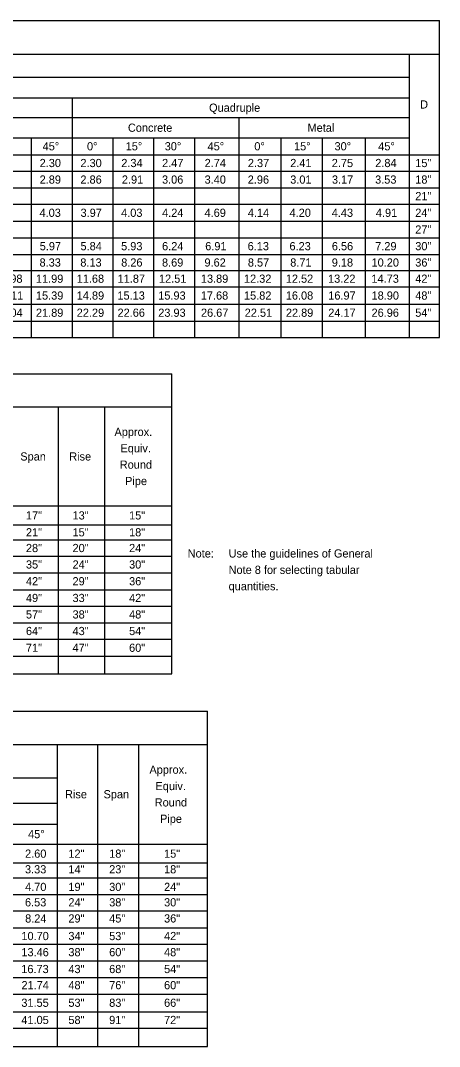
# Model space of a CAD drawing. Extents: x 10029 to 10796, y 10063 to 10519.
# Drawn here: x 10616.8 to 10795.9, y 10063.2 to 10502 of the extents above; entities that cross this region are included whole.
import ezdxf

# ---------------------------------------------------------------- set-up
doc = ezdxf.new("R2010")
doc.units = 0
doc.layers.add('Default', color=7, linetype='Continuous')
doc.layers.add('Dimension', color=7, linetype='Continuous')

msp = doc.modelspace()

# ---------------------------------------------------------------- linework, layer by layer
at = {"layer": 'Default'}
for p, q in [((10028.97, 10502.01), (10795.89, 10502.01)), ((10795.89, 10366.47), (10795.89, 10502.01)), ((10028.97, 10487.65), (10795.89, 10487.65)), ((10783.03, 10366.47), (10783.03, 10487.65)), ((10326.86, 10477.72), (10783.03, 10477.72)), ((10326.86, 10468.97), (10783.03, 10468.97)), ((10638.95, 10366.47), (10638.95, 10468.97)), ((10042.36, 10460.49), (10783.03, 10460.49)), ((10710.2, 10366.47), (10710.2, 10460.49)), ((10244.78, 10451.88), (10783.03, 10451.88)), ((10621.51, 10366.47), (10621.51, 10451.88)), ((10656.39, 10366.47), (10656.39, 10451.88)), ((10673.82, 10366.47), (10673.82, 10451.88)), ((10691.26, 10366.47), (10691.26, 10451.88)), ((10728.19, 10366.47), (10728.19, 10451.88)), ((10745.95, 10366.47), (10745.95, 10451.88)), ((10764.33, 10366.47), (10764.33, 10451.88)), ((10795.89, 10366.47), (10795.89, 10451.88)), ((10028.97, 10444.58), (10795.89, 10444.58)), ((10028.97, 10437.55), (10795.89, 10437.55)), ((10028.97, 10430.43), (10795.89, 10430.43)), ((10028.97, 10423.41), (10795.89, 10423.41)), ((10028.97, 10416.18), (10795.89, 10416.18)), ((10028.97, 10409.08), (10795.89, 10409.08)), ((10028.97, 10401.92), (10795.89, 10401.92)), ((10028.97, 10395.12), (10795.89, 10395.12)), ((10028.97, 10388.08), (10795.89, 10388.08)), ((10028.97, 10380.7), (10795.89, 10380.7)), ((10028.97, 10373.4), (10795.89, 10373.4)), ((10028.97, 10366.47), (10795.89, 10366.47)), ((10039.72, 10350.86), (10681.45, 10350.86)), ((10681.45, 10222.58), (10681.45, 10350.86)), ((10039.72, 10336.74), (10681.45, 10336.74)), ((10633.08, 10222.58), (10633.08, 10336.74)), ((10652.82, 10222.58), (10652.82, 10336.74)), ((10039.72, 10294.39), (10681.45, 10294.39)), ((10039.72, 10286.34), (10681.45, 10286.34)), ((10039.72, 10279.92), (10681.45, 10279.92)), ((10039.72, 10272.9), (10681.45, 10272.9)), ((10039.72, 10265.84), (10681.45, 10265.84)), ((10039.72, 10258.56), (10681.45, 10258.56)), ((10039.72, 10251.55), (10681.45, 10251.55)), ((10039.72, 10244.47), (10681.45, 10244.47)), ((10039.72, 10237.36), (10681.45, 10237.36)), ((10039.72, 10230.15), (10681.45, 10230.15)), ((10039.72, 10222.58), (10681.45, 10222.58)), ((10040.76, 10206.56), (10696.75, 10206.56)), ((10696.75, 10063.22), (10696.75, 10206.56)), ((10040.76, 10192.44), (10696.75, 10192.44)), ((10632.55, 10063.22), (10632.55, 10192.44)), ((10649.82, 10063.22), (10649.82, 10192.44)), ((10667.43, 10063.22), (10667.43, 10192.44)), ((10386.23, 10178.05), (10632.55, 10178.05)), ((10084.96, 10167.22), (10632.55, 10167.22)), ((10303.39, 10158.32), (10632.55, 10158.32)), ((10040.76, 10149.78), (10696.75, 10149.78)), ((10040.76, 10141.72), (10696.75, 10141.72)), ((10040.76, 10135.31), (10696.75, 10135.31)), ((10040.76, 10128.29), (10696.75, 10128.29)), ((10040.76, 10121.22), (10696.75, 10121.22)), ((10040.76, 10113.95), (10696.75, 10113.95)), ((10040.76, 10106.93), (10696.75, 10106.93)), ((10040.76, 10099.86), (10696.75, 10099.86)), ((10040.76, 10092.75), (10696.75, 10092.75)), ((10040.76, 10085.54), (10696.75, 10085.54)), ((10040.76, 10077.97), (10696.75, 10077.97)), ((10040.76, 10071.08), (10696.75, 10071.08)), ((10040.76, 10063.22), (10696.75, 10063.22))]:
    msp.add_line(p, q, dxfattribs=at)

# ---------------------------------------------------------------- texts
at = {"layer": 'Dimension'}
for s, p in [('Quadruple', (10697.4, 10462.98)), ('D', (10787.63, 10464.37)), ('Concrete', (10662.7, 10454.43)), ('Metal', (10739.48, 10454.43)), ('45°', (10626.25, 10446.48)), ('0°', (10645.21, 10446.48)), ('15°', (10661.75, 10446.48)), ('30°', (10678.43, 10446.48)), ('45°', (10696.76, 10446.48)), ('0°', (10716.74, 10446.48)), ('15°', (10733.72, 10446.48)), ('30°', (10751.03, 10446.48)), ('45°', (10769.71, 10446.48)), ('20.04', (10605.99, 10375.3)), ('21.89', (10623.39, 10375.3)), ('22.51', (10712.64, 10375.3)), ('22.89', (10730.24, 10375.3)), ('24.17', (10748.35, 10375.3)), ('26.96', (10766.85, 10375.3)), ('Approx.', (10656.96, 10324.32)), ('Equiv.', (10659.53, 10317.32)), ('Span', (10616.7, 10313.82)), ('Rise', (10637.61, 10313.82)), ('Round', (10659.22, 10310.32)), ('Pipe', (10661.51, 10303.32)), ('Approx.', (10671.91, 10179.86)), ('Equiv.', (10674.48, 10172.86)), ('Rise', (10635.84, 10169.36)), ('Span', (10652.29, 10169.36)), ('Round', (10674.17, 10165.86)), ('Pipe', (10676.45, 10158.86)), ('45°', (10620.03, 10152.3))]:
    msp.add_text(s, height=3.5, dxfattribs=at).set_placement(p)
for s, p in [('2.30', (10624.97, 10439.32)), ('2.30', (10642.41, 10439.32)), ('2.34', (10659.87, 10439.32)), ('2.47', (10677.32, 10439.32)), ('2.74', (10695.5, 10439.32)), ('2.37', (10713.98, 10439.32)), ('2.41', (10732.09, 10439.32)), ('2.75', (10749.85, 10439.32)), ('2.84', (10768.45, 10439.32)), ('15"', (10785.54, 10439.32)), ('2.89', (10624.97, 10432.24)), ('2.86', (10642.4, 10432.24)), ('2.91', (10660.12, 10432.24)), ('3.06', (10677.28, 10432.24)), ('3.40', (10695.48, 10432.24)), ('2.96', (10713.93, 10432.24)), ('3.01', (10732.09, 10432.24)), ('3.17', (10749.92, 10432.24)), ('3.53', (10768.38, 10432.24)), ('18"', (10785.54, 10432.24)), ('21"', (10785.54, 10425.17)), ('4.03', (10624.93, 10418.04)), ('3.97', (10642.45, 10418.04)), ('4.03', (10659.8, 10418.04)), ('4.24', (10677.31, 10418.04)), ('4.69', (10695.47, 10418.04)), ('4.14', (10713.97, 10418.04)), ('4.20', (10731.81, 10418.04)), ('4.43', (10749.84, 10418.04)), ('4.91', (10768.7, 10418.04)), ('24"', (10785.54, 10418.04)), ('27"', (10785.54, 10410.88)), ('5.97', (10625.01, 10403.75)), ('5.84', (10642.44, 10403.75)), ('5.93', (10659.8, 10403.75)), ('6.24', (10677.31, 10403.75)), ('6.91', (10695.75, 10403.75)), ('6.13', (10713.89, 10403.75)), ('6.23', (10731.77, 10403.75)), ('6.56', (10749.88, 10403.75)), ('7.29', (10768.42, 10403.75)), ('30"', (10785.54, 10403.75)), ('8.33', (10624.93, 10396.77)), ('8.13', (10642.36, 10396.77)), ('8.26', (10659.84, 10396.77)), ('8.69', (10677.28, 10396.77)), ('9.62', (10695.43, 10396.77)), ('8.57', (10713.98, 10396.77)), ('8.71', (10732.09, 10396.77)), ('9.18', (10749.85, 10396.77)), ('10.20', (10766.86, 10396.77)), ('36"', (10785.54, 10396.77)), ('10.98', (10605.93, 10389.85)), ('11.99', (10623.39, 10389.85)), ('11.68', (10640.81, 10389.85)), ('11.87', (10658.31, 10389.85)), ('12.51', (10675.99, 10389.85)), ('13.89', (10693.9, 10389.85)), ('12.32', (10712.33, 10389.85)), ('12.52', (10730.2, 10389.85)), ('13.22', (10748.27, 10389.85)), ('14.73', (10766.81, 10389.85)), ('42"', (10785.54, 10389.85)), ('14.11', (10606.23, 10382.64)), ('15.39', (10623.39, 10382.64)), ('14.89', (10640.83, 10382.64)), ('15.13', (10658.23, 10382.64)), ('15.93', (10675.67, 10382.64)), ('17.68', (10693.87, 10382.64)), ('15.82', (10712.33, 10382.64)), ('16.08', (10730.21, 10382.64)), ('16.97', (10748.35, 10382.64)), ('18.90', (10766.86, 10382.64)), ('48"', (10785.54, 10382.64)), ('22.29', (10640.83, 10375.3)), ('22.66', (10658.27, 10375.3)), ('23.93', (10675.67, 10375.3)), ('26.67', (10693.94, 10375.3)), ('54"', (10785.54, 10375.3)), ('17"', (10619.11, 10288.61)), ('13"', (10639.03, 10288.61)), ('15"', (10663.21, 10288.61)), ('21"', (10619.11, 10281.38)), ('15"', (10639.03, 10281.38)), ('18"', (10663.21, 10281.38)), ('28"', (10619.11, 10274.66)), ('20"', (10639.03, 10274.66)), ('24"', (10663.21, 10274.66)), ('Note:', (10688.26, 10272.34)), ('Use the guidelines of General ', (10705.76, 10272.34)), ('35"', (10619.11, 10267.62)), ('24"', (10639.03, 10267.62)), ('30"', (10663.21, 10267.62)), ('Note 8 for selecting tabular ', (10705.76, 10265.34)), ('42"', (10619.11, 10260.45)), ('29"', (10639.03, 10260.45)), ('36"', (10663.21, 10260.45)), ('quantities.', (10705.76, 10258.34)), ('49"', (10619.11, 10253.3)), ('33"', (10639.03, 10253.3)), ('42"', (10663.21, 10253.3)), ('57"', (10619.11, 10246.26)), ('38"', (10639.03, 10246.26)), ('48"', (10663.21, 10246.26)), ('64"', (10619.11, 10239.17)), ('43"', (10639.03, 10239.17)), ('54"', (10663.21, 10239.17)), ('71"', (10619.11, 10232.01)), ('47"', (10639.03, 10232.01)), ('60"', (10663.21, 10232.01)), ('2.60', (10618.75, 10143.95)), ('12"', (10637.26, 10143.95)), ('18"', (10654.7, 10143.95)), ('15"', (10678.16, 10143.95)), ('3.33', (10618.7, 10137.25)), ('14"', (10637.26, 10137.25)), ('23"', (10654.7, 10137.25)), ('18"', (10678.16, 10137.25)), ('4.70', (10618.75, 10129.73)), ('19"', (10637.26, 10129.73)), ('30"', (10654.7, 10129.73)), ('24"', (10678.16, 10129.73)), ('6.53', (10618.7, 10123.13)), ('24"', (10637.26, 10123.13)), ('38"', (10654.7, 10123.13)), ('30"', (10678.16, 10123.13)), ('8.24', (10618.77, 10116.23)), ('29"', (10637.26, 10116.23)), ('45"', (10654.7, 10116.23)), ('36"', (10678.16, 10116.23)), ('10.70', (10617.18, 10108.71)), ('34"', (10637.26, 10108.71)), ('53"', (10654.7, 10108.71)), ('42"', (10678.16, 10108.71)), ('13.46', (10617.17, 10101.81)), ('38"', (10637.26, 10101.81)), ('60"', (10654.7, 10101.81)), ('48"', (10678.16, 10101.81)), ('16.73', (10617.13, 10094.6)), ('43"', (10637.26, 10094.6)), ('68"', (10654.7, 10094.6)), ('54"', (10678.16, 10094.6)), ('21.74', (10617.2, 10087.7)), ('48"', (10637.26, 10087.7)), ('76"', (10654.7, 10087.7)), ('60"', (10678.16, 10087.7)), ('31.55', (10617.15, 10080.18)), ('53"', (10637.26, 10080.18)), ('83"', (10654.7, 10080.18)), ('66"', (10678.16, 10080.18)), ('41.05', (10617.15, 10072.81)), ('58"', (10637.26, 10072.81)), ('91"', (10654.7, 10072.81)), ('72"', (10678.16, 10072.81))]:
    msp.add_text(s, height=3.5, rotation=0, dxfattribs=at).set_placement(p)

doc.saveas('drawing.dxf')
